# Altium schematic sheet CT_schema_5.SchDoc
size 284 x 147 mm
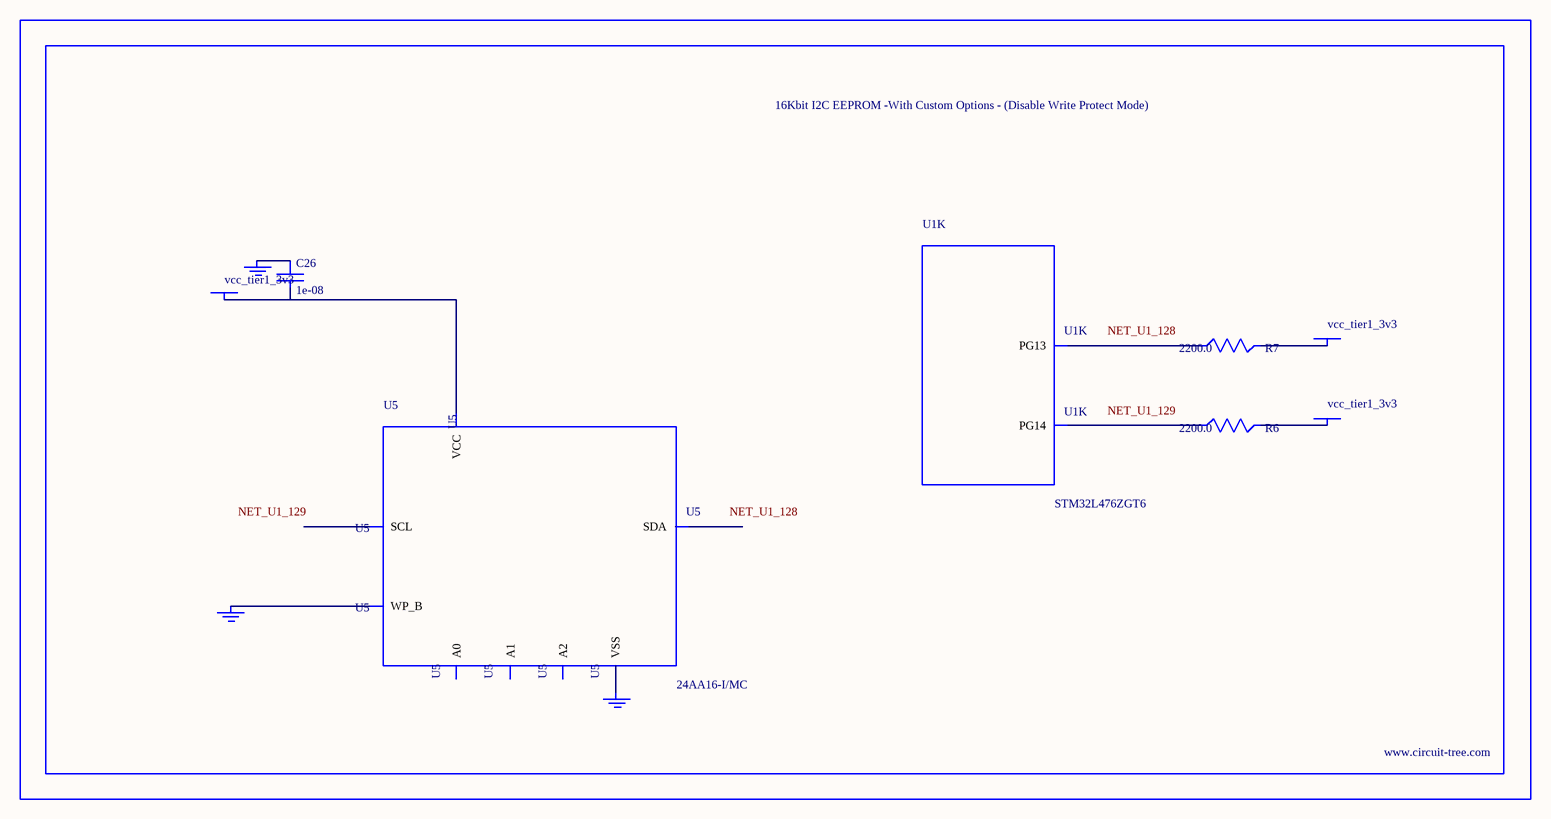
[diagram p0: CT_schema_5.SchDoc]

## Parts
BORDER4  (no value)
C26  1e-08  [C0402]
GND_INSTANCE_4_0  (no value)
GND_INSTANCE_4_1  (no value)
GND_INSTANCE_4_2  (no value)
POWER_INSTANCE_4_0  vcc_tier1_3v3
POWER_INSTANCE_4_1  vcc_tier1_3v3
POWER_INSTANCE_4_2  vcc_tier1_3v3
R6  2200.0  [R0603]
R7  2200.0  [R0603]
U1  STM32L476ZGT6  [LQFP144]  (part K of 13)
U5  24AA16-I/MC  [TDFN-8/6MM]

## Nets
NetC26_1: C26.1 GND_INSTANCE_4_1.0(GND)
NetC26_2: C26.2 POWER_INSTANCE_4_0.0(PWR) U5.8(VCC)
NetGND_INSTANCE_4_0_0: GND_INSTANCE_4_0.0(GND) U5.7(WP_B)
NetGND_INSTANCE_4_2_0: GND_INSTANCE_4_2.0(GND) U5.4(VSS)
NetPOWER_INSTANCE_4_1_0: POWER_INSTANCE_4_1.0(PWR) R7.2
NetPOWER_INSTANCE_4_2_0: POWER_INSTANCE_4_2.0(PWR) R6.2
NetR6_1: R6.1 U1.129(PG14)
NetR7_1: R7.1 U1.128(PG13)

Not connected (* = marked no-connect by the designer): U5 1(A0) 2(A1) 3(A2) 5(SDA) 6(SCL)

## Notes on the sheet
- Labels drawn without touching a wire or pin: NET_U1_128, NET_U1_129

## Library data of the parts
BORDER4 = BORDER_PAGE4
C26 = C0402C103K3RAC
GND_INSTANCE_4_0-GND_INSTANCE_4_2 = GND
POWER_INSTANCE_4_0-POWER_INSTANCE_4_2 = PWR
R6 R7 = RC0603JR-072K2L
